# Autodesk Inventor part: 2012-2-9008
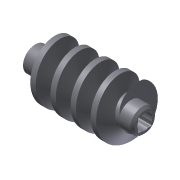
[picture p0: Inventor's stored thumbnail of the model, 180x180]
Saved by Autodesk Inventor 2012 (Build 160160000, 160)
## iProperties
Created: 2011-12
Part Number: 2012-2-9008
Material: Steel, Mild
Document SubType Name: Modeling
Designer: Admin
Categories: <?xml version="1.0" encoding="UTF-16"?> <MemberInstance><Categories><FamilyTemplate><FamilyTemplateParameter ValueType="xs:double" Id="1" ObjectReferenceKey="da
Density: 7.86 g/cm^3
Description: Worm
CustomPartVersion: 1
Author: Admin
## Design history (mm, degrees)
body "Solid1"
extrude "Base Body" new body stored distance "d6" = 24 (= da_b); taper "d7" = 0 deg
chamfer "Chamfer1" distance "d8" = 1.12103 (= fd_cham1); stored, may be unused: second distance "d9" = 3.08 (= 0.5 x fd_cham2), angle "d47" = 45 deg
chamfer "Chamfer2" distance "d10" = 1.12103 (= fd_cham1); stored, may be unused: second distance "d11" = 3.08 (= 0.5 x fd_cham2), angle "d48" = 45 deg
sketch "Tooth Sketch"
  geometry: L1 (0, 8.408)-(0, 3.989) reference; L2 (-17.024, 5.868)-(-15.882, 2.73); L3 (-14.906, 2.73)-(-13.764, 5.868); L4 (-17.686, 0)-(-13.102, 0) reference; L5 (-17.024, 5.868)-(-15.394, 5.868); L6 (-15.394, 5.868)-(-13.764, 5.868); L7 (-15.882, 2.73)-(-15.394, 2.73); L8 (-15.394, 2.73)-(-14.906, 2.73); L9 (-15.394, 4.41)-(-14.294, 4.41); L10 (-15.394, 5.868)-(-15.394, 2.73)
  constraints: 16 end point, 3 equal length, 3 parallel, 2 collinear, 2 point on line
  dimensions: "d24" = 110 deg angle of L7 L2 (computed from da_alfat); "d25" = 15.3938 distance from line of L1 L5.end (= fd_dist); "d26" = 1.09956 distance of L9.start L9.end (= 0.25 x da_px); "d27" = 2.73 distance between parallel lines of L4 L7 (= 0.5 x da_df); "d28" = 4.41 distance between parallel lines of L4 L9 (= 0.5 x da_d); "d29" = 5.8681 distance between parallel lines of L4 L5 (= 0.505 x da_da)
feature "Tooth" pitch "d30" = 4.39823 (computed from da_px, da_z); turns "d32" = 8 (= fd_n); dims "d31" = 10, "d33" = 0, angle "d34" = 90 deg, angle "d35" = 90 deg, "d36" = 0, "d37" = 0, "d70" = 10, "da_rightdir" = 10 [user parameter]
pattern_circular "Tooth Pattern" dims angle "d46" = 360 deg
feature "Left Tooth" pitch "d62" = 4.39823 (computed from da_px, da_z); turns "d64" = 8 (= fd_n); dims "d63" = 10, "d65" = 0, angle "d66" = 90 deg, angle "d67" = 90 deg, "d68" = 0, "d69" = 0, "d76" = 10, "da_rightdir" = 10 [user parameter]
pattern_circular "Left Tooth Pattern" dims angle "d73" = 360 deg
mirror "Mirror1"
hole "Hole1" diameter "d91" = 3.3 (= 1.1 x d101); stored, may be unused: countersink angle "d95" = 90 deg, drill point angle "d97" = 118 deg; dims "d92" = 6, "d93" = 4, "d94" = 2, "d96" = 8, "d115" = 10, "d116" = 10
chamfer "Chamfer3" distance "d86" = 0.5; stored, may be unused: second distance "d87" = 2, angle "d88" = 45 deg
chamfer "Chamfer4" distance "d98" = 0.05; stored, may be unused: second distance "d99" = 2, angle "d100" = 45 deg
sketch "Sketch7"
  geometry: L1 (-1.5, -1.5)-(1.5, -1.5); L2 (1.5, -1.5)-(1.5, 1.5); L3 (1.5, 1.5)-(-1.5, 1.5); L4 (-1.5, 1.5)-(-1.5, -1.5); L5 (1.5, -1.5)-(-1.5, 1.5); 2 further points
  constraints: 10 end point, 2 parallel, 2 perpendicular, 1 coincident, 1 horizontal, 1 midpoint
  dimensions: "d101" = 3 distance of L2.end L3.end
extrude "Extrusion3" cut sketch "Sketch7" stored distance "d104" = 10; taper "d105" = 0 deg
fillet "Fillet1" dims "d108" = 0.25
node "Base Body Sketch" dims "d5" = 11.62 (= da_da)
sketch "Sketch5"
  geometry: C1 r 5.81 at (0, 0) reference; C2 r 4.41 at (0, 0)
  constraints: 1 centre point, 1 coincident
  dimensions: "d59" = 8.82 diameter of C2 (= da_d)
body "Srf1"
feature "Pitch Diameter" dims "d60" = 10, "d61" = 0
sketch "Sketch6"
  geometry: C1 r 2.68 at (-0.319, -0.208); C2 r 6.81 at (-0.319, -0.208); A1 r 2.73 centre (-0.319, -0.208) between (-2.63, -1.661) and (-2.155, 1.812) reference
  constraints: 2 centre point, 1 coincident, 1 concentric
  dimensions: "d85" = 0.05 radial gap between concentric circles of A1 C1; "d109" = 13.62 diameter of C2; "d114" = 5.36 diameter of C1 (derived)
extrude "Extrusion2" cut sketch "Sketch6" taper "d83" = 0 deg; distance "d84" = 3
other parameters: "da_b" = 24 [user parameter; used in 3 equation terms], "da_df" = 5.46 [user parameter; used in 2 equation terms], "da_da" = 11.62 [user parameter; used in 3 equation terms], "fd_cham2" = 6.16 (= da_da - da_df) [user parameter; used in 3 equation terms], "fd_cham1" = 1.12103 (= 0.181985 x fd_cham2) [user parameter; used in 2 equation terms], "da_d" = 8.82 [user parameter; used in 2 equation terms], "da_px" = 4.39823 [user parameter; used in 5 equation terms], "fd_dist" = 15.3938 (computed from da_b, da_px) [user parameter; used in 1 equation term], "fd_n" = 8 (computed from da_b, da_px) [user parameter; used in 2 equation terms], "da_alfat" = 20 deg [user parameter; used in 1 equation term], "d12" = 110 deg (derived), "d14" = 3.1425 (derived), "d50" = 0, "d54" = 0, "d56" = 0, "d77" = 0, "d80" = 0
